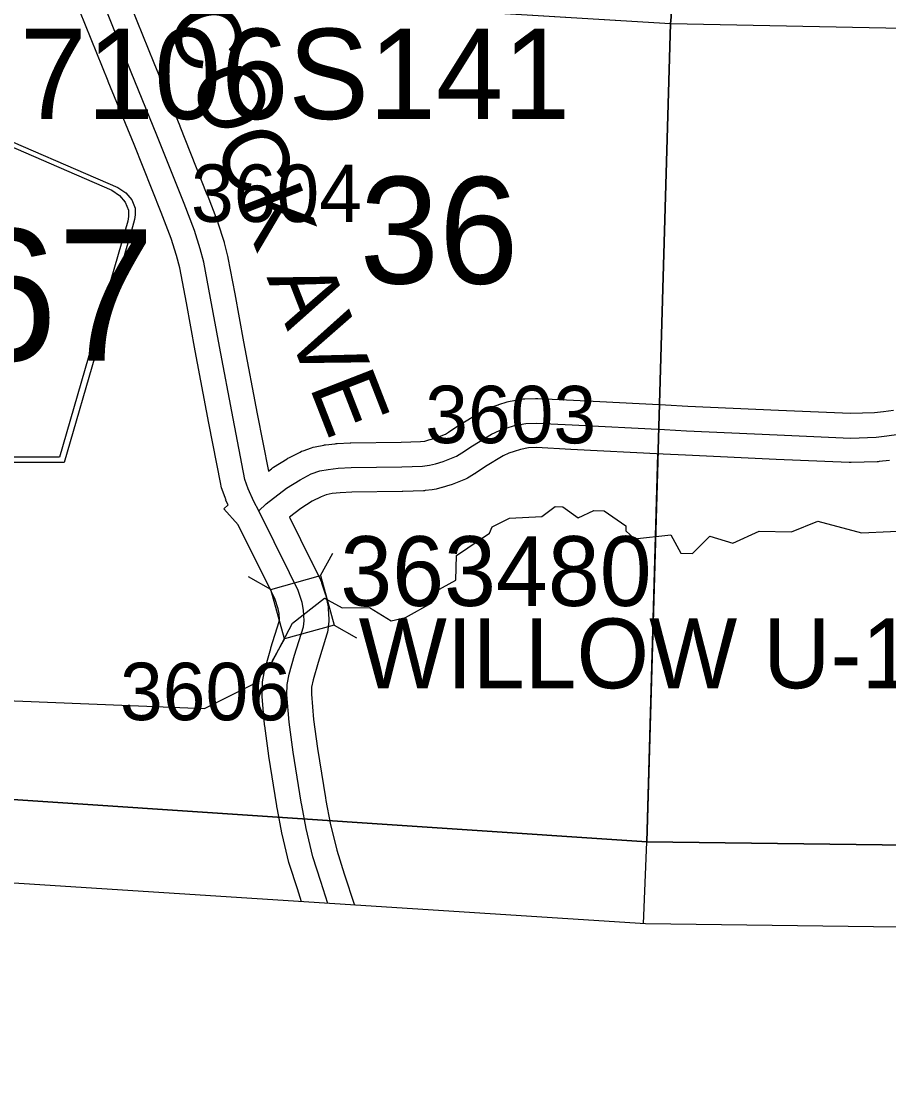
# Model space of a CAD drawing. Extents: x -157.2 to -99.3, y 12.2 to 46.2.
# Drawn here: x -129.982 to -128.926, y 16.19 to 17.501 of the extents above; entities that cross this region are included whole.
import ezdxf

# ---------------------------------------------------------------- set-up
doc = ezdxf.new("R2010")
doc.units = 0
for name, color, linetype in [('tdCoClipBndry', 7, 'Continuous'), ('tdCoCoBndry', 7, 'Continuous'), ('tdCoCoBndryPart', 7, 'Continuous'), ('tdCoHydroRiver', 7, 'Continuous'), ('tdCoSecRdNmbr', 7, 'Continuous'), ('tdCoSecRdTxt', 7, 'Continuous'), ('tdCoSecRteBand', 7, 'Continuous'), ('tdCoSecRteCL', 7, 'Continuous'), ('tdCoSectLine', 7, 'Continuous'), ('tdCoSectLinePart', 7, 'Continuous'), ('tdCoSectNmbr', 7, 'Continuous'), ('tdCoShieldCoRte', 7, 'Continuous'), ('tdCoStrucPriMaintName', 7, 'Continuous'), ('tdCoStrucSec', 7, 'Continuous'), ('tdCoStrucSecCoName', 7, 'Continuous'), ('tdCoStrucSecFHWANum', 7, 'Continuous'), ('tdCoSurfGravel', 7, 'Continuous'), ('tdCoTwpBndry', 7, 'Continuous'), ('tdCoTwpBndryShd', 7, 'Continuous')]:
    doc.layers.add(name, color=color, linetype=linetype)

msp = doc.modelspace()

# ---------------------------------------------------------------- linework, layer by layer
at = {"layer": 'tdCoClipBndry'}
msp.add_lwpolyline([(-122.302, 16.1905), (-125.2749, 16.2789), (-127.2441, 16.3602), (-128.2341, 16.3892), (-129.2216, 16.4019), (-131.209, 16.5298), (-132.1838, 16.5754), (-133.1873, 16.6004), (-134.1718, 16.6514), (-135.1611, 16.7141)], dxfattribs=at)
at = {"layer": 'tdCoCoBndry'}
msp.add_lwpolyline([(-135.1553, 16.8138), (-134.1666, 16.7512), (-133.1821, 16.7002), (-132.2019, 16.6758), (-132.1802, 16.6753), (-131.2035, 16.6296), (-130.2056, 16.5679), (-129.2203, 16.5019), (-128.232, 16.4892), (-127.2406, 16.4601), (-126.2534, 16.4199), (-125.2718, 16.3788), (-124.2853, 16.348)], dxfattribs=at)
at = {"layer": 'tdCoCoBndryPart'}
for points in [[(-131.0502, 16.6201), (-130.2056, 16.5679), (-129.6683, 16.5319)], [(-129.6069, 16.5278), (-129.2203, 16.5019), (-128.232, 16.4892), (-127.4726, 16.4669)]]:
    msp.add_lwpolyline(points, dxfattribs=at)
at = {"layer": 'tdCoHydroRiver'}
for points in [[(-129.7592, 16.6643), (-129.6998, 16.6941), (-129.677, 16.7203), (-129.6518, 16.7685), (-129.613, 16.7989), (-129.5913, 16.7872), (-129.5581, 16.7877), (-129.5318, 16.7711), (-129.5143, 16.7754), (-129.4822, 16.7933), (-129.477, 16.8074), (-129.4529, 16.8209), (-129.452, 16.8509), (-129.4118, 16.8781), (-129.4084, 16.8859), (-129.3875, 16.8963), (-129.348, 16.8982), (-129.3318, 16.9104), (-129.3224, 16.9101), (-129.3038, 16.8969), (-129.2846, 16.9058), (-129.272, 16.9054), (-129.2457, 16.8872), (-129.2459, 16.8809), (-129.2352, 16.8711), (-129.1908, 16.8761), (-129.1788, 16.8536), (-129.1647, 16.8532), (-129.1435, 16.8746), (-129.1153, 16.8659), (-129.0833, 16.8807), (-129.0439, 16.8795), (-129.0119, 16.8928), (-128.9587, 16.8785), (-128.8528, 16.8832)], [(-130.5623, 16.6761), (-130.5443, 16.6961), (-129.7592, 16.6643)]]:
    msp.add_lwpolyline(points, dxfattribs=at)
at = {"layer": 'tdCoSecRteBand'}
for points in [[(-129.8551, 17.5369), (-129.8206, 17.4512), (-129.7891, 17.3743), (-129.7891, 17.3742), (-129.789, 17.374), (-129.756, 17.2909), (-129.7559, 17.2907), (-129.7558, 17.2906), (-129.7432, 17.2578), (-129.7429, 17.2569), (-129.7427, 17.2561), (-129.7355, 17.2337), (-129.7352, 17.2328), (-129.735, 17.232), (-129.7308, 17.2154), (-129.7306, 17.2146), (-129.7304, 17.2137), (-129.7221, 17.1698), (-129.722, 17.1696), (-129.722, 17.1695), (-129.7114, 17.1112), (-129.6947, 17.0236), (-129.6812, 16.9536)], [(-129.6408, 16.4289), (-129.6459, 16.4446), (-129.6459, 16.4446), (-129.6459, 16.4446), (-129.6555, 16.4744), (-129.6558, 16.4755), (-129.6561, 16.4766), (-129.6645, 16.5114), (-129.6647, 16.5122), (-129.6648, 16.513), (-129.67, 16.5413), (-129.6707, 16.545), (-129.6708, 16.5454), (-129.6709, 16.5458), (-129.6805, 16.6064), (-129.6805, 16.6067), (-129.6805, 16.6069), (-129.6857, 16.6434), (-129.6859, 16.6443), (-129.6859, 16.6452), (-129.6886, 16.6785), (-129.6888, 16.68), (-129.6887, 16.6815), (-129.6885, 16.6941), (-129.6884, 16.6966), (-129.6879, 16.6992), (-129.6855, 16.712), (-129.6852, 16.7133), (-129.6848, 16.7147), (-129.6782, 16.7376), (-129.6781, 16.7379), (-129.678, 16.7382), (-129.6679, 16.7705), (-129.6676, 16.7725), (-129.6681, 16.7803), (-129.6693, 16.7859), (-129.6729, 16.7971), (-129.6822, 16.8167), (-129.7065, 16.8651), (-129.7066, 16.8651), (-129.7181, 16.8884), (-129.7354, 16.9078), (-129.7302, 16.9125), (-129.7333, 16.9187), (-129.7328, 16.919), (-129.7329, 16.9193), (-129.7334, 16.9205), (-129.7339, 16.9216), (-129.7381, 16.9332), (-129.7389, 16.9355), (-129.7393, 16.9378), (-129.7536, 17.0123), (-129.7536, 17.0123), (-129.7536, 17.0123), (-129.7704, 17.1001), (-129.7704, 17.1002), (-129.7704, 17.1004), (-129.781, 17.1587), (-129.7892, 17.2015), (-129.793, 17.2163), (-129.7996, 17.2371), (-129.8118, 17.2689), (-129.8447, 17.3517), (-129.8762, 17.4285), (-129.8762, 17.4286), (-129.8763, 17.4287), (-129.9107, 17.5142)], [(-129.6812, 16.9536), (-129.6774, 16.9565), (-129.6762, 16.9575), (-129.6749, 16.9583), (-129.6584, 16.9687), (-129.6573, 16.9694), (-129.6561, 16.97), (-129.6425, 16.9769), (-129.6408, 16.9778), (-129.639, 16.9784), (-129.6286, 16.9821), (-129.6265, 16.9829), (-129.6242, 16.9833), (-129.6138, 16.9853), (-129.6128, 16.9855), (-129.6118, 16.9856), (-129.5998, 16.9871), (-129.5986, 16.9872), (-129.5975, 16.9873), (-129.5817, 16.988), (-129.5812, 16.988), (-129.5807, 16.988), (-129.5194, 16.9888), (-129.4958, 16.9897), (-129.4906, 16.9903), (-129.4859, 16.9916), (-129.4781, 16.9939), (-129.4656, 16.9988), (-129.4618, 17.0011), (-129.4491, 17.0095), (-129.4487, 17.0098), (-129.4482, 17.0101), (-129.425, 17.0241), (-129.4238, 17.0249), (-129.4226, 17.0255), (-129.413, 17.0301), (-129.4114, 17.0309), (-129.4098, 17.0315), (-129.4014, 17.0344), (-129.401, 17.0346), (-129.4005, 17.0347), (-129.3904, 17.0379), (-129.3885, 17.0385), (-129.3866, 17.0389), (-129.3728, 17.0413), (-129.3707, 17.0417), (-129.3686, 17.0418), (-129.3556, 17.0423), (-129.3542, 17.0423), (-129.3529, 17.0423), (-129.3095, 17.04), (-129.3095, 17.04), (-129.3095, 17.04), (-129.1973, 17.0343), (-129.1703, 17.0329), (-129.0599, 17.028), (-128.972, 17.0241), (-128.9428, 17.025), (-128.9318, 17.0263), (-128.9195, 17.0281)], [(-128.9244, 16.9667), (-128.9372, 16.9652), (-128.9384, 16.9651), (-128.9397, 16.9651), (-128.9713, 16.9641), (-128.9724, 16.964), (-128.9735, 16.9641), (-129.0626, 16.968), (-129.0626, 16.968), (-129.0626, 16.968), (-129.173, 16.973), (-129.1731, 16.973), (-129.1732, 16.973), (-129.2004, 16.9744), (-129.3126, 16.9801), (-129.3546, 16.9823), (-129.3643, 16.9819), (-129.3741, 16.9802), (-129.3819, 16.9777), (-129.3882, 16.9755), (-129.3951, 16.9721), (-129.4166, 16.9591), (-129.4292, 16.9508), (-129.4296, 16.9505), (-129.43, 16.9503), (-129.4364, 16.9463), (-129.4386, 16.9449), (-129.4411, 16.9439), (-129.4574, 16.9375), (-129.4587, 16.937), (-129.46, 16.9366), (-129.4694, 16.9339), (-129.4696, 16.9339), (-129.4698, 16.9338), (-129.4769, 16.9318), (-129.4792, 16.9312), (-129.4815, 16.931), (-129.4901, 16.93), (-129.4912, 16.9298), (-129.4923, 16.9298), (-129.5175, 16.9288), (-129.5179, 16.9288), (-129.5183, 16.9288), (-129.5794, 16.9281), (-129.5936, 16.9274), (-129.6036, 16.9262), (-129.6107, 16.9248), (-129.617, 16.9225), (-129.6277, 16.9171), (-129.6418, 16.9083), (-129.6556, 16.8975), (-129.6285, 16.8433), (-129.6283, 16.843), (-129.6282, 16.8428), (-129.6179, 16.8211), (-129.617, 16.8193), (-129.6164, 16.8174), (-129.6117, 16.8028), (-129.6112, 16.8013), (-129.6109, 16.7998), (-129.6089, 16.7904), (-129.6084, 16.7882), (-129.6083, 16.786), (-129.6076, 16.7731), (-129.6074, 16.7703), (-129.6078, 16.7675), (-129.6088, 16.7601), (-129.6091, 16.7575), (-129.6099, 16.7551), (-129.6206, 16.7206), (-129.6268, 16.6993), (-129.6285, 16.6903), (-129.6287, 16.6818), (-129.6262, 16.651), (-129.6212, 16.6156), (-129.6117, 16.5555), (-129.611, 16.5522), (-129.606, 16.5246), (-129.598, 16.4918), (-129.5888, 16.463), (-129.5764, 16.4247)]]:
    msp.add_lwpolyline(points, dxfattribs=at)
at = {"layer": 'tdCoSecRteCL'}
for points in [[(-129.693, 16.9053), (-129.6988, 16.9168), (-129.7057, 16.9319), (-129.7098, 16.9434), (-129.7242, 17.0179), (-129.7409, 17.1057), (-129.7515, 17.1642), (-129.7599, 17.2081), (-129.7641, 17.2246), (-129.7713, 17.247), (-129.7838, 17.2798), (-129.8169, 17.3629), (-129.8484, 17.4399), (-129.883, 17.5257), (-129.8907, 17.5439), (-129.9108, 17.5915), (-129.9523, 17.6877), (-129.9554, 17.6993), (-129.9616, 17.7141), (-129.9671, 17.7531), (-129.9742, 17.8098), (-129.9767, 17.8276)], [(-129.693, 16.9053), (-129.6837, 16.9137), (-129.659, 16.9329), (-129.6425, 16.9432), (-129.6289, 16.9502), (-129.6186, 16.9539), (-129.6082, 16.9558), (-129.5961, 16.9573), (-129.5803, 16.958), (-129.5187, 16.9588), (-129.4935, 16.9598), (-129.4849, 16.9608), (-129.4777, 16.9627), (-129.4684, 16.9654), (-129.4521, 16.9719), (-129.4457, 16.9758), (-129.4326, 16.9844), (-129.4094, 16.9985), (-129.3998, 17.0032), (-129.3914, 17.0061), (-129.3813, 17.0093), (-129.3675, 17.0118), (-129.3544, 17.0123), (-129.311, 17.0101), (-129.1988, 17.0043), (-129.1717, 17.0029), (-129.0612, 16.998), (-128.9722, 16.994), (-128.9406, 16.995), (-128.9278, 16.9965), (-128.9133, 16.9987)], [(-129.6086, 16.4268), (-129.6173, 16.4538), (-129.6269, 16.4836), (-129.6353, 16.5184), (-129.6405, 16.5467), (-129.6412, 16.5505), (-129.6508, 16.6111), (-129.656, 16.6476), (-129.6587, 16.6809), (-129.6585, 16.6935), (-129.656, 16.7063), (-129.6494, 16.7293), (-129.6385, 16.764), (-129.6375, 16.7714), (-129.6383, 16.7842), (-129.6402, 16.7936), (-129.6449, 16.8082), (-129.6553, 16.8299), (-129.693, 16.9053)]]:
    msp.add_lwpolyline(points, dxfattribs=at)
at = {"layer": 'tdCoSectLine'}
for points in [[(-129.1913, 17.4992), (-129.1907, 17.5067), (-129.1634, 18.5052)], [(-130.1788, 17.5591), (-129.1913, 17.4992)], [(-129.2203, 16.5019), (-129.1913, 17.4992)], [(-129.1913, 17.4992), (-128.1825, 17.4789)], [(-130.2056, 16.5679), (-129.2203, 16.5019)], [(-129.2243, 16.4021), (-129.2203, 16.5019)], [(-129.2203, 16.5019), (-128.232, 16.4892)]]:
    msp.add_lwpolyline(points, dxfattribs=at)
at = {"layer": 'tdCoSectLinePart'}
for points in [[(-129.1913, 17.4992), (-129.1907, 17.5067), (-129.178, 17.9711)], [(-129.8567, 17.5396), (-129.1913, 17.4992)], [(-129.2048, 17.0351), (-129.1913, 17.4992)], [(-129.1913, 17.4992), (-128.1825, 17.4789)], [(-129.2203, 16.5019), (-129.2066, 16.9748)], [(-130.2056, 16.5679), (-129.6683, 16.5319)], [(-129.6069, 16.5278), (-129.2203, 16.5019)], [(-129.2243, 16.4021), (-129.2203, 16.5019)], [(-129.2203, 16.5019), (-128.232, 16.4892)]]:
    msp.add_lwpolyline(points, dxfattribs=at)
at = {"layer": 'tdCoShieldCoRte'}
for points in [[(-130.1694, 16.9641), (-130.2513, 17.247), (-130.2552, 17.2602), (-130.2559, 17.2661), (-130.2559, 17.2739), (-130.2517, 17.2842), (-130.2444, 17.2927), (-130.2348, 17.2993), (-130.0676, 17.3717), (-130.0601, 17.3733), (-130.0496, 17.3742), (-130.0392, 17.3733), (-130.0317, 17.3717), (-129.8644, 17.2993), (-129.8548, 17.2927), (-129.8476, 17.2842), (-129.8433, 17.2739), (-129.8433, 17.2661), (-129.8441, 17.2602), (-129.8479, 17.247), (-129.9299, 16.9641)], [(-130.1635, 16.9705), (-130.2433, 17.2457), (-130.247, 17.2584), (-130.2477, 17.264), (-130.2477, 17.2715), (-130.2436, 17.2814), (-130.2366, 17.2896), (-130.2274, 17.296), (-130.0669, 17.3654), (-130.0596, 17.367), (-130.0496, 17.3679), (-130.0396, 17.367), (-130.0324, 17.3654), (-129.8718, 17.296), (-129.8626, 17.2896), (-129.8556, 17.2814), (-129.8516, 17.2715), (-129.8516, 17.264), (-129.8523, 17.2584), (-129.856, 17.2457), (-129.9357, 16.9705)]]:
    msp.add_lwpolyline(points, close=True, dxfattribs=at)
at = {"layer": 'tdCoStrucSec'}
for p, q in [((-129.6179, 16.8263), (-129.6025, 16.8535)), ((-129.6782, 16.8095), (-129.7054, 16.8249)), ((-129.6011, 16.766), (-129.5738, 16.7506)), ((-129.6614, 16.7492), (-129.6768, 16.7219))]:
    msp.add_line(p, q, dxfattribs=at)
msp.add_lwpolyline([(-129.6614, 16.7492), (-129.6782, 16.8095), (-129.6179, 16.8263), (-129.6011, 16.766)], close=True, dxfattribs=at)
at = {"layer": 'tdCoSurfGravel'}
msp.add_line((-129.6405, 16.5467), (-129.6412, 16.5505), dxfattribs=at)
for points in [[(-129.693, 16.9053), (-129.6988, 16.9168), (-129.7057, 16.9319), (-129.7098, 16.9434), (-129.7242, 17.0179), (-129.7409, 17.1057), (-129.7515, 17.1642), (-129.7599, 17.2081), (-129.7641, 17.2246), (-129.7713, 17.247), (-129.7838, 17.2798), (-129.8169, 17.3629), (-129.8484, 17.4399), (-129.883, 17.5257), (-129.8907, 17.5439), (-129.9108, 17.5915), (-129.9523, 17.6877), (-129.9554, 17.6993)], [(-129.693, 16.9053), (-129.6837, 16.9137), (-129.659, 16.9329), (-129.6425, 16.9432), (-129.6289, 16.9502), (-129.6186, 16.9539), (-129.6082, 16.9558), (-129.5961, 16.9573), (-129.5803, 16.958), (-129.5187, 16.9588), (-129.4935, 16.9598), (-129.4849, 16.9608), (-129.4777, 16.9627), (-129.4684, 16.9654), (-129.4521, 16.9719), (-129.4457, 16.9758), (-129.4326, 16.9844), (-129.4094, 16.9985), (-129.3998, 17.0032), (-129.3914, 17.0061), (-129.3813, 17.0093), (-129.3675, 17.0118), (-129.3544, 17.0123), (-129.311, 17.0101), (-129.1988, 17.0043)], [(-129.1988, 17.0043), (-129.1717, 17.0029), (-129.0612, 16.998), (-128.9722, 16.994), (-128.9406, 16.995), (-128.9278, 16.9965), (-128.9133, 16.9987)], [(-129.6412, 16.5505), (-129.6508, 16.6111), (-129.656, 16.6476), (-129.6587, 16.6809), (-129.6585, 16.6935), (-129.656, 16.7063), (-129.6494, 16.7293), (-129.6385, 16.764), (-129.6375, 16.7714), (-129.6383, 16.7842), (-129.6402, 16.7936), (-129.6449, 16.8082), (-129.6553, 16.8299), (-129.693, 16.9053)], [(-129.6086, 16.4268), (-129.6173, 16.4538), (-129.6269, 16.4836), (-129.6353, 16.5184), (-129.6405, 16.5467)]]:
    msp.add_lwpolyline(points, dxfattribs=at)
at = {"layer": 'tdCoTwpBndry'}
msp.add_lwpolyline([(-129.2203, 16.5019), (-129.1913, 17.4992), (-129.1907, 17.5067), (-129.178, 17.9716)], dxfattribs=at)
at = {"layer": 'tdCoTwpBndryShd'}
for points in [[(-128.6576, 34.667), (-128.6804, 33.5187), (-128.7065, 32.5225), (-128.7373, 31.5164), (-128.7661, 30.5223), (-128.7967, 29.5185), (-128.8255, 28.521), (-128.8657, 27.4917), (-128.8964, 26.4888), (-128.93, 25.491), (-128.9664, 24.4882), (-129.007, 23.4876), (-129.0347, 22.4935), (-129.0534, 21.5204), (-129.0947, 20.5153), (-129.1281, 19.5112), (-129.1634, 18.5052), (-129.1907, 17.5067), (-129.1913, 17.4992), (-129.2203, 16.5019)], [(-124.2853, 16.348), (-125.2718, 16.3788), (-126.2534, 16.4199), (-127.2406, 16.4601), (-128.232, 16.4892), (-129.2203, 16.5019), (-130.2056, 16.5679), (-131.2035, 16.6296), (-132.1802, 16.6753), (-132.2019, 16.6758), (-133.1821, 16.7002), (-134.1666, 16.7512), (-135.1553, 16.8138)]]:
    msp.add_lwpolyline(points, dxfattribs=at)

# ---------------------------------------------------------------- texts
at = {"layer": 'tdCoSecRdNmbr'}
for s, rotation, p in [('3604', 359.9018, (-129.7755, 17.2574)), ('3603', 359.9021, (-129.4902, 16.9878)), ('3606', 359.9018, (-129.862, 16.6503))]:
    msp.add_text(s, height=0.07, rotation=rotation, dxfattribs=at).set_placement(p)
at = {"layer": 'tdCoSecRdTxt'}
msp.add_text('HANCOCK AVE', height=0.08, rotation=291.2936, dxfattribs=at).set_placement((-129.8886, 17.7159))
at = {"layer": 'tdCoSectNmbr'}
msp.add_text('36', height=0.13, rotation=359.9019, dxfattribs=at).set_placement((-129.5701, 17.1823))
at = {"layer": 'tdCoShieldCoRte'}
msp.add_text('K67', height=0.16, dxfattribs=at).set_placement((-130.2001, 17.0884))
at = {"layer": 'tdCoStrucPriMaintName'}
msp.add_text('97106S141', height=0.11, dxfattribs=at).set_placement((-130.0659, 17.3827))
at = {"layer": 'tdCoStrucSecCoName'}
msp.add_text('WILLOW U-105', height=0.085, dxfattribs=at).set_placement((-129.5711, 16.6891))
at = {"layer": 'tdCoStrucSecFHWANum'}
msp.add_text('363480', height=0.085, dxfattribs=at).set_placement((-129.5936, 16.7894))

doc.saveas('drawing.dxf')
